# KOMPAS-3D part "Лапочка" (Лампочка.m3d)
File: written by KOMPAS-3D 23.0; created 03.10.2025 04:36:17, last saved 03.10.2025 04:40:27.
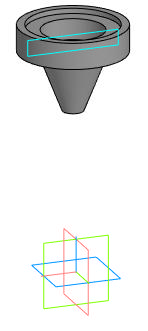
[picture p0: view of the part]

Document properties: Автор: Inspektor_Kot; Полное имя файла: I:\Autodesk Inventor Projects\ИМ-ИТ ЦД\Вариант 14\Лапочка.m3d

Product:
- Part/product: Лапочка
    Масса: 0.398086

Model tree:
1. Нормальная плоскость:1  (with: Элемент вращения:1)
2. Эскиз:1  (with: Элемент вращения:1)
3. Элемент вращения:1
     Угол 1 = 360
4. Элемент выдавливания:1  (with: Элемент вращения:1)
     Расстояние 1 = 16
5. Элемент выдавливания:2  (with: Элемент вращения:1)
     Расстояние 1 = 4
6. Элемент выдавливания:3  (with: Элемент вращения:1)
     Расстояние 1 = 20

Referenced files in I:\Autodesk Inventor Projects\ИМ-ИТ ЦД\Вариант 14\: Фонарик.a3d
